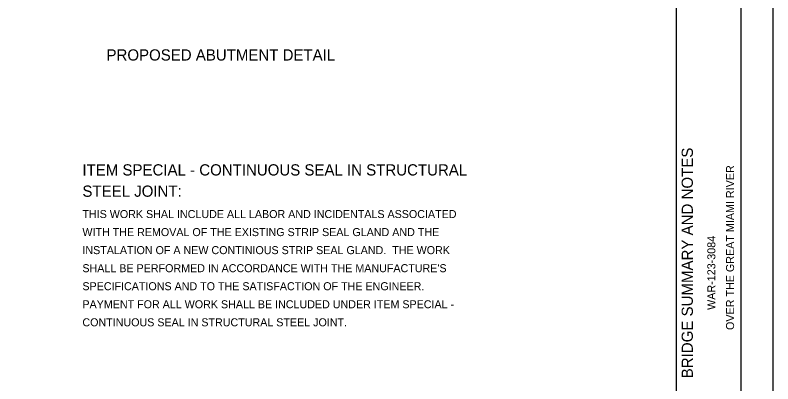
# Model space of a CAD drawing. Extents: x -706 to 14950, y -1867 to 6417.
# Drawn here: x 454 to 808.2, y -1526.3 to -1354.2 of the extents above; entities that cross this region are included whole.
import ezdxf

# ---------------------------------------------------------------- set-up
doc = ezdxf.new("R2010")
doc.units = 0
for name, color, linetype in [('Level 1', 7, 'Continuous'), ('Level 41', 7, 'Continuous'), ('Level 44', 7, 'Continuous')]:
    doc.layers.add(name, color=color, linetype=linetype)

msp = doc.modelspace()

# ---------------------------------------------------------------- linework, layer by layer
at = {"layer": 'Level 1'}
msp.add_line((763.17, -1721.66), (763.17, -1091.66), dxfattribs=at)
for points in [[(-211.83, -1076.66), (808.17, -1076.66), (808.17, -1736.66), (-211.83, -1736.66)], [(-151.83, -1091.66), (793.17, -1091.66), (793.17, -1721.66), (-151.83, -1721.66)]]:
    msp.add_lwpolyline(points, close=True, dxfattribs=at)

# ---------------------------------------------------------------- texts
for s, height, p in [('   BRIDGE SUMMARY AND NOTES  ', 5.25, (770.8, -1529.58)), ('OVER THE GREAT MIAMI RIVER', 3.75, (790.05, -1501.19)), ('       WAR-123-3084       ', 3.75, (781.3, -1501.56))]:
    msp.add_text(s, height=height, rotation=90, dxfattribs=at).set_placement(p)
at = {"layer": 'Level 41'}
for s, p in [('ITEM SPECIAL - CONTINUOUS SEAL IN STRUCTURAL ', (485.48, -1429.08)), ('STEEL JOINT:', (485.48, -1439.01))]:
    msp.add_text(s, height=5.25, dxfattribs=at).set_placement(p)
at = {"layer": 'Level 44'}
for s, height, p in [('PROPOSED ABUTMENT DETAIL', 5.25, (496.74, -1375.43)), ('THIS WORK SHAL INCLUDE ALL LABOR AND INCIDENTALS ASSOCIATED', 3.7407, (485.48, -1448.94)), ('WITH THE REMOVAL OF THE EXISTING STRIP SEAL GLAND AND THE ', 3.7407, (485.48, -1457.36)), ('INSTALATION OF A NEW CONTINIOUS STRIP SEAL GLAND.  THE WORK ', 3.7407, (485.48, -1465.78)), ("SHALL BE PERFORMED IN ACCORDANCE WITH THE MANUFACTURE'S ", 3.7407, (485.48, -1474.21)), ('SPECIFICATIONS AND TO THE SATISFACTION OF THE ENGINEER. ', 3.7407, (485.48, -1482.63)), ('PAYMENT FOR ALL WORK SHALL BE INCLUDED UNDER ITEM SPECIAL -', 3.7407, (485.48, -1491.05)), ('CONTINUOUS SEAL IN STRUCTURAL STEEL JOINT.', 3.7407, (485.48, -1499.47))]:
    msp.add_text(s, height=height, dxfattribs=at).set_placement(p)

doc.saveas('drawing.dxf')
